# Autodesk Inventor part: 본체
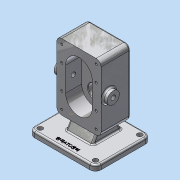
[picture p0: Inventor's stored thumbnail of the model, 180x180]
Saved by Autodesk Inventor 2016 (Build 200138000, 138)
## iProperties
Created: 2020-04
Part Number: 본체
Material: 알루미늄 6061
Document SubType Name: Modeling
Designer: Administrator
Density: 2.7 g/cm^3
Appearance: 알루미늄 - 평지
Mass: 1472.54 g
Surface Area: 818.394 cm^2
Volume: 545.387 cm^3
Author: Administrator
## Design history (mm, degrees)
sketch "스케치1"
  geometry: L1 (-60, 50)-(60, 50); L2 (60, 50)-(60, -50); L3 (60, -50)-(-60, -50); L4 (-60, -50)-(-60, 50); L5 (-60, 50)-(60, -50); L6 (60, 50)-(-60, -50); 1 further point
  constraints: 12 end point, 2 midpoint, 2 parallel, 1 horizontal, 1 perpendicular
  dimensions: "d0" = 120 distance of L2.end L3.end; "d1" = 100 distance of L1.end L2.end
extrude "돌출1" new body sketch "스케치1" distance "d2" = 10; taper "d3" = 0 deg
node "작업 평면1"
sketch "스케치3"
  geometry: L1 (20, -150)-(100, -150); L2 (100, -150)-(100, -30); L3 (100, -30)-(20, -30); L4 (20, -30)-(20, -150); L5 (20, -150)-(100, -30); L6 (100, -150)-(20, -30); L7 (0, 0)-(120, 0) reference; 3 further points
  constraints: 12 end point, 3 midpoint, 2 parallel, 1 horizontal, 1 perpendicular, 1 vertical alignment
  dimensions: "d8" = 80 distance of L1.start L1.end; "d9" = 150 distance between parallel lines of L7 L1; "d10" = 120 distance between parallel lines of L1 L3
extrude "돌출2" join sketch "스케치3" distance "d11" = 53; taper "d12" = 0 deg
sketch "스케치5"
  geometry: L1 (20, -150)-(100, -150) reference; L2 (0, 0)-(120, 0) reference; C1 r 19 at (60, -112); 2 further points
  constraints: 1 centre point, 1 midpoint, 1 vertical alignment
  dimensions: "d14" = 38 diameter of C1; "d15" = 38 distance from line of C1.centre L1
extrude "돌출3" join sketch "스케치5" distance "d16" = 17; taper "d17" = 0 deg
sketch "스케치6"
  geometry: L1 (-24, 33)-(24, 33); L2 (24, 33)-(24, -20); L3 (24, -20)-(-24, -20); L4 (-24, -20)-(-24, 33); L5 (-24, 33)-(24, -20); L6 (24, 33)-(-24, -20); L7 (-60, 50)-(60, 50) reference; 3 further points
  constraints: 12 end point, 3 midpoint, 2 parallel, 1 horizontal, 1 perpendicular, 1 vertical alignment
  dimensions: "d18" = 53 distance of L1.end L2.end; "d19" = 48 distance of L2.end L3.end; "d20" = 17 distance between parallel lines of L7 L1
extrude "돌출4" join sketch "스케치6" stored distance "d21" = 17; taper "d22" = 0 deg
sketch "스케치7"
  geometry: L1 (-20, 53)-(-140, 53) reference; L2 (0, 53)-(-20, 53) reference; L3 (0, 0)-(-20, 0) reference; L4 (-140, 0)-(-20, 0) reference; L5 (0, 70)-(0, -30) reference; L6 (0, 0)-(-20, 11.547); L7 (-20, 11.547)-(-20, 0); L8 (-20, 0)-(0, 0); L9 (0, 53)-(-20, 53); L10 (-20, 53)-(-20, 41.453); L11 (-20, 41.453)-(0, 53); L12 (-140, 53)-(-140, 0) reference; 1 further point
  constraints: 12 end point, 2 point on line, 2 vertical, 1 perpendicular
  dimensions: "d23" = 60 deg angle of L5 L11; "d24" = 60 deg angle of L5 L6; "d25" = 120 distance between parallel lines of L10 L12; "d26" = 120 distance between parallel lines of L12 L7
extrude "돌출5" cut sketch "스케치7" stored distance "d27" = 17; taper "d28" = 0 deg
fillet "모깎기1" dims "d29" = 9
sketch "스케치8"
  geometry: A1 r 9 centre (91, 141) between (100, 141) and (91, 150) reference; A2 r 9 centre (29, 141) between (29, 150) and (20, 141) reference; A3 r 9 centre (29, 39) between (20, 39) and (29, 30) reference; A4 r 9 centre (91, 39) between (91, 30) and (100, 39) reference; 9 further points
  constraints: 4 coincident, 4 vertical alignment
  dimensions: "d30" = 29 distance of point (29, 141) point (29, 112); "d31" = 102 distance of point (29, 141) point (29, 39) (derived); "d32" = 44 distance of point (29, 68) point (29, 112); "d33" = 29 distance of point (91, 141) point (91, 112); "d34" = 44 distance of point (91, 68) point (91, 112)
hole "구멍1" sketch "스케치8" at (91, 141), (29, 141), (91, 39), (29, 39), (91, 112), (91, 68), (29, 112), (29, 68) diameter "d35" = 4.134; stored, may be unused: countersink angle "d39" = 90 deg, drill point angle "d41" = 118 deg; dims "d36" = 10, "d37" = 4, "d38" = 2, "d40" = 12
sketch "스케치10"
  geometry: L1 (60, 112)-(60, 68); L2 (36, 112)-(36, 68); L3 (84, 68)-(84, 112); L4 (91, 150)-(29, 150) reference; L5 (20, 141)-(20, 39) reference; L6 (29, 30)-(91, 30) reference; L7 (100, 39)-(100, 141) reference; L8 (120, 0)-(0, 0) reference; C1 r 2.067 at (29, 112) reference; C2 r 2.067 at (91, 112) reference; C3 r 2.067 at (91, 39) reference; C4 r 2.067 at (91, 141) reference; C5 r 2.067 at (29, 141) reference; C6 r 2.067 at (29, 39) reference; C7 r 2.067 at (91, 68) reference; C8 r 2.067 at (29, 68) reference; A1 r 24 centre (60, 112) between (84, 112) and (36, 112); A2 r 24 centre (60, 68) between (36, 68) and (84, 68); A3 r 9 centre (91, 141) between (100, 141) and (91, 150) reference; A4 r 9 centre (29, 141) between (29, 150) and (20, 141) reference; A5 r 9 centre (29, 39) between (20, 39) and (29, 30) reference; A6 r 9 centre (91, 39) between (91, 30) and (100, 39) reference; 3 further points
  constraints: 8 end point, 4 point on circle, 4 tangent, 2 centre point, 2 horizontal alignment, 2 midpoint, 1 parallel, 1 vertical, 1 vertical alignment
  dimensions: "d42" = 24 radius of A1
extrude "돌출6" cut sketch "스케치10" distance "d43" = 29; taper "d44" = 0 deg
sketch "스케치11"
  geometry: L1 (-20, 112)-(-20, 112) reference; L2 (-20, 112)-(9, 112) reference; L3 (9, 112)-(9, 112) reference; L4 (-20, 112)-(9, 112) reference; L5 (-20, 112)-(9, 112) reference; L6 (50, 93)-(50, 131) reference; L7 (33, 131)-(50, 131) reference; L8 (33, 93)-(50, 93) reference; L9 (9, 112)-(50, 112); L10 (9, 112)-(9, 136) reference; L11 (9, 112)-(9, 124.5); L12 (9, 124.5)-(24, 124.5); L13 (24, 124.5)-(24, 120.5); L14 (24, 120.5)-(42.7, 120.5); L15 (42.7, 120.5)-(42.7, 126); L16 (42.7, 126)-(50, 126); L17 (50, 126)-(50, 112); 1 further point
  constraints: 16 end point, 4 perpendicular, 2 point on line, 1 collinear, 1 horizontal, 1 midpoint
  dimensions: "d45" = 25 diameter of L12 L9; "d46" = 17 diameter of L14 L9; "d47" = 28 diameter of L16 L9; "d48" = 15 distance between parallel lines of L11 L13; "d49" = 7.3 distance between parallel lines of L17 L15
revolve "회전1" sketch "스케치11" stored, may be unused: angle "d50" = 90 deg
sketch "스케치12"
  geometry: C1 r 12.5 at (60, 68); A1 r 24 centre (60, 68) between (36, 68) and (84, 68) reference; 1 further point
  constraints: 1 centre point, 1 coincident
  dimensions: "d51" = 25 diameter of C1
extrude "돌출7" cut sketch "스케치12" distance "d52" = 15; taper "d53" = 0 deg
chamfer "모따기1" distance "d54" = 0.7; stored, may be unused: second distance "d55" = 2, angle "d56" = 30 deg
fillet "모깎기2" dims "d57" = 0.5
sketch "스케치14"
  geometry: L1 (102, -53)-(0, -53) reference; L2 (141, 17)-(141, -83) reference; C1 r 11 at (51, -39); 2 further points
  constraints: 1 centre point, 1 coincident
  dimensions: "d58" = 14 distance from line of L1 point (51, -39); "d59" = 90 distance from line of L2 point (51, -39); "d60" = 22 diameter of C1
extrude "돌출8" join sketch "스케치14" distance "d61" = 8; taper "d62" = 0 deg
hole "구멍2" diameter "d65" = 8.376; stored, may be unused: countersink angle "d69" = 90 deg, drill point angle "d71" = 118 deg; dims "d63" = 10, "d64" = 10, "d66" = 20, "d67" = 4, "d68" = 2, "d70" = 27.3
fillet "모깎기3" dims "d72" = 10
sketch "스케치16"
  geometry: A1 r 10 centre (50, 40) between (60, 40) and (50, 50) reference; A2 r 10 centre (50, -40) between (50, -50) and (60, -40) reference; A3 r 10 centre (-50, -40) between (-60, -40) and (-50, -50) reference; A4 r 10 centre (-50, 40) between (-50, 50) and (-60, 40) reference; 5 further points
  constraints: 4 coincident
hole "구멍3" sketch "스케치16" at (50, 40), (-50, 40), (-50, -40), (50, -40) diameter "d73" = 9; stored, may be unused: countersink angle "d77" = 90 deg, drill point angle "d79" = 118 deg; dims "d74" = 20, "d75" = 4, "d76" = 2, "d78" = 27.3
fillet "모깎기4" dims "d80" = 3
fillet "모깎기5" dims "d81" = 3
chamfer "모따기2" distance "d82" = 1; stored, may be unused: second distance "d83" = 2, angle "d84" = 30 deg
sketch "스케치17"
  geometry: L1 (-50, -50)-(50, -50) reference; L2 (-60, 40)-(-60, -40) reference; 2 further points
  constraints: 1 other
  dimensions: "d85" = 10 distance from line of L1 point (0, -40); "d86" = 60 distance from line of L2 point (0, -40)
feature "엠보싱1" sketch "스케치17" dims "d0" = 120, "d1" = 100, "d87" = 0.5, "d88" = 0
node "솔리드1"
mirror "대칭1"
node "투영된 루프1"
node "투영된 루프2"
other parameters: "d7" = -17
